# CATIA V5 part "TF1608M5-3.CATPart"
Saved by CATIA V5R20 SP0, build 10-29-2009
Part number: TF1608M5-3
Revision: ANY
Definition: UNKNOWN
Nomenclature: TF1608M5-3
Source: Unknown
Bounding box of the stored display mesh (mm): x -3.662 to 3.662, y 0 to 3.55, z -3.85 to 3.85
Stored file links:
  C:\Users\Utente\Desktop\IO LAVORO\3D X SITO CF\CUMSA\3D files RCM\RCM 163808\TF1608M5-3.CATPart
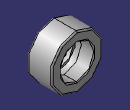
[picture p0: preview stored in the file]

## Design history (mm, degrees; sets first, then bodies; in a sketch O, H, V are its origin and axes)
Body1 "Cortar-Revolución1" (main body)
  Solid1: solid without history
